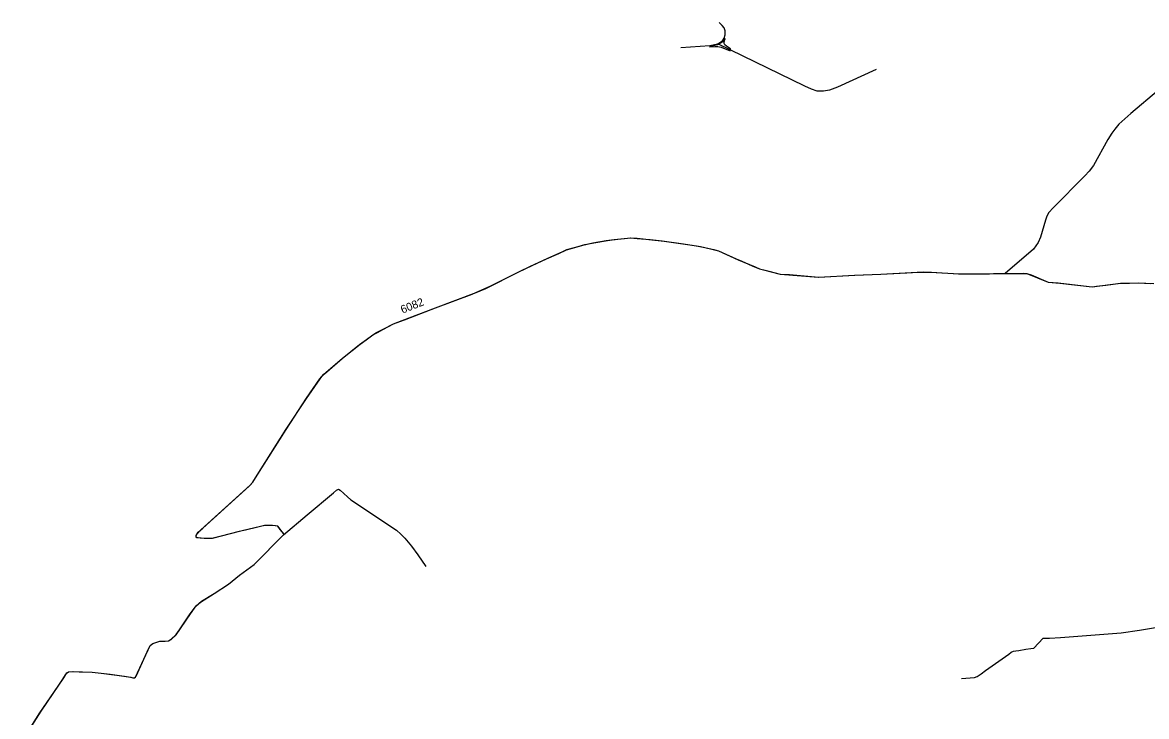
# Model space of a CAD drawing. Extents: x -444937 to -436355, y -1135022 to -1129798.
# Drawn here: x -444613 to -443209, y -1132915 to -1132048 of the extents above; entities that cross this region are included whole.
import ezdxf

# ---------------------------------------------------------------- set-up
doc = ezdxf.new("R2010")
doc.units = 0
doc.layers.add('Vrstva 12', color=7, linetype='Continuous')
doc.layers.add('Vrstva 75', color=7, linetype='Continuous')

msp = doc.modelspace()

# ---------------------------------------------------------------- linework, layer by layer
at = {"layer": 'Vrstva 12'}
for points in [[(-443790.5, -1132079.3), (-443754.5, -1132076.8), (-443744.6, -1132074.4), (-443738.7, -1132071), (-443736.3, -1132067.6), (-443735.4, -1132063.3), (-443735.4, -1132058.4), (-443736.6, -1132054.7), (-443739, -1132051.6), (-443742.8, -1132047.9)], [(-443546.4, -1132106.7), (-443594.8, -1132128.6), (-443605, -1132132.6), (-443612.4, -1132133.9), (-443620.1, -1132133.6), (-443627.5, -1132131.4), (-443635.5, -1132127.4), (-443744.6, -1132074.4)], [(-443193.7, -1132132.4), (-443228.1, -1132161.8), (-443243.2, -1132175.1), (-443248.2, -1132181.2), (-443252.1, -1132186.4), (-443257.1, -1132194.3), (-443275, -1132226.5), (-443280.2, -1132233.8), (-443285.8, -1132239.7), (-443325.5, -1132279.4), (-443330.7, -1132285.2), (-443333.2, -1132289.9), (-443335, -1132295.1), (-443341, -1132316.1), (-443344.2, -1132323), (-443350.1, -1132331.2), (-443385.1, -1132361.7)], [(-444286.4, -1132687.8), (-444291.4, -1132681.3), (-444294.5, -1132677.6), (-444297.8, -1132676.9), (-444301.8, -1132676.7), (-444311, -1132676.8), (-444317.7, -1132678.2), (-444337.3, -1132683), (-444376.8, -1132692.9), (-444381.9, -1132692.9), (-444386.3, -1132692.8), (-444390.1, -1132692.6), (-444391.2, -1132692.5), (-444394, -1132692.2), (-444394.6, -1132692.1), (-444395.8, -1132691.5), (-444396.3, -1132690.2), (-444396.3, -1132689.1), (-444395.6, -1132687.4), (-444390.6, -1132682), (-444328.9, -1132626.3), (-444325.6, -1132622.4), (-444322.2, -1132617.1), (-444284, -1132556.4), (-444258.4, -1132517.7), (-444241.6, -1132493.3), (-444239.4, -1132490.2), (-444236.1, -1132487), (-444213.9, -1132467.8), (-444192.2, -1132450.5), (-444183.6, -1132444.3), (-444175.6, -1132438.3), (-444169.9, -1132435.3), (-444163, -1132431.6), (-444149.6, -1132424.7), (-444139, -1132420.5), (-444097.1, -1132404.7), (-444046.4, -1132385.5), (-444034.5, -1132380.2), (-443993, -1132359.6), (-443976.4, -1132351.6), (-443958.6, -1132343.2), (-443943.2, -1132336.5), (-443933.5, -1132332.2), (-443923.2, -1132329), (-443913, -1132326.1), (-443900.5, -1132323.4), (-443884.1, -1132320.4), (-443873.9, -1132319.3)], [(-443873.9, -1132319.3), (-443860.9, -1132317.8), (-443853.7, -1132317.1), (-443845.1, -1132317.7), (-443829, -1132319.2), (-443813.9, -1132320.8), (-443787.5, -1132324.4), (-443774.1, -1132326.5), (-443765.9, -1132328.1), (-443753.7, -1132330.8), (-443743.6, -1132333.5), (-443718.8, -1132344.5), (-443697.9, -1132353.5), (-443692.3, -1132355.7), (-443687.3, -1132357), (-443666.5, -1132362.3), (-443654.9, -1132363.1), (-443618.1, -1132366.1), (-443573.6, -1132363.9), (-443540.7, -1132362.4), (-443508.2, -1132360.9), (-443493.5, -1132359.8), (-443478.8, -1132359.8), (-443442.9, -1132361.9), (-443404.8, -1132362.1), (-443385.1, -1132361.7), (-443362.3, -1132361.3), (-443358.1, -1132361.5), (-443353, -1132363.4), (-443331.5, -1132372.4), (-443319.2, -1132373.3), (-443276.5, -1132378.3), (-443271, -1132377.6), (-443259.7, -1132376.4), (-443241.2, -1132373.6), (-443230.1, -1132373.6), (-443218.9, -1132373.2), (-443203.8, -1132374.1)], [(-444613.4, -1132945.4), (-444590.2, -1132908.7), (-444567.2, -1132874.9), (-444563.8, -1132870), (-444559.6, -1132863.3), (-444557.8, -1132861), (-444556, -1132859.6), (-444550.6, -1132859.3), (-444542.8, -1132859.6), (-444526.3, -1132859.9), (-444515, -1132861.1), (-444486, -1132865.2), (-444478.6, -1132866.3), (-444475.4, -1132867), (-444473.5, -1132866.9), (-444472, -1132866.1), (-444454, -1132826.8), (-444450.4, -1132824.1), (-444445.7, -1132822.4), (-444441.8, -1132821.1), (-444435, -1132821.1), (-444430.8, -1132820.8), (-444427.7, -1132819.1), (-444421.2, -1132813.3), (-444403.6, -1132786.9), (-444396.3, -1132776.9), (-444390.9, -1132772.4), (-444374, -1132761.8), (-444355.9, -1132749.9), (-444342.4, -1132738.9), (-444323.9, -1132725.4), (-444287.2, -1132688.4), (-444257.5, -1132663.2), (-444224.7, -1132635.8), (-444220.9, -1132632.4), (-444218.5, -1132631.4), (-444216.2, -1132632.7), (-444211.7, -1132636.8), (-444207.2, -1132640.8), (-444202.9, -1132644.4), (-444146.1, -1132682.4), (-444140.4, -1132687.3), (-444135.5, -1132692.5), (-444127.1, -1132702.6), (-444119.5, -1132713.5), (-444109.5, -1132728.1)], [(-443439.9, -1132867.8), (-443423.7, -1132866.7), (-443420.1, -1132865.6), (-443415.5, -1132862.2), (-443409.8, -1132858), (-443380.8, -1132837.3), (-443377.7, -1132835.1), (-443374.7, -1132833.9), (-443371.9, -1132833.2), (-443368.2, -1132832.8), (-443359.4, -1132831.3), (-443353.1, -1132830.6), (-443349.3, -1132830.1), (-443338, -1132817.7), (-443334.6, -1132817.5), (-443330, -1132817.3), (-443316.2, -1132816.5), (-443240.3, -1132811), (-443217.5, -1132807.6), (-443192.3, -1132803.2)]]:
    msp.add_lwpolyline(points, dxfattribs=at)
msp.add_lwpolyline([(-443755, -1132078.3), (-443748.3, -1132077.9), (-443744.2, -1132078), (-443740.1, -1132078.9), (-443729, -1132083.2), (-443728.4, -1132080.7), (-443733.4, -1132077.4), (-443735.6, -1132075.6), (-443736.5, -1132074.1), (-443736.6, -1132072), (-443735.4, -1132068), (-443738.3, -1132072), (-443744.7, -1132075.7)], close=True, dxfattribs=at)
at = {"layer": 'Vrstva 75'}
for points in [[(-444286.2, -1132687.7), (-444291.4, -1132681.5), (-444294.5, -1132677.6), (-444297.1, -1132677), (-444301.1, -1132676.7), (-444310.3, -1132676.7), (-444314.3, -1132677.5), (-444319.4, -1132678.6), (-444334.8, -1132682.3), (-444342.5, -1132684.2), (-444376.4, -1132692.8), (-444385.1, -1132692.8), (-444390.9, -1132692.3), (-444394, -1132692.2), (-444395.5, -1132691.9), (-444396.4, -1132690.7), (-444396.3, -1132689.1), (-444393.8, -1132685.1), (-444388.2, -1132679.8), (-444330.1, -1132627.3), (-444325.6, -1132622.4), (-444322.2, -1132617.1), (-444284.1, -1132556.6), (-444258.5, -1132517.6), (-444241.9, -1132493.5), (-444239.4, -1132490.2), (-444237, -1132487.6), (-444213.5, -1132467.4), (-444191.4, -1132450), (-444183.9, -1132444.6), (-444175.6, -1132438.3), (-444170.8, -1132435.6), (-444162.5, -1132431.3), (-444149.6, -1132424.7), (-444136.2, -1132419.5), (-444097.1, -1132404.6), (-444051.4, -1132387.3), (-444028.3, -1132376.9), (-443993, -1132359.6), (-443978.7, -1132352.6), (-443957, -1132342.4), (-443938.2, -1132334.1), (-443933, -1132331.8), (-443921.8, -1132328.6), (-443910.6, -1132325.4), (-443897, -1132322.7), (-443882.1, -1132320.2), (-443876.5, -1132319.6)], [(-443876.5, -1132319.6), (-443865.6, -1132318.2), (-443853, -1132317.1), (-443845.1, -1132317.6), (-443826.9, -1132319.4), (-443811.3, -1132321.1), (-443785.2, -1132324.8), (-443771.1, -1132327), (-443762.6, -1132328.8), (-443749.6, -1132331.7), (-443743.6, -1132333.3), (-443721.3, -1132343.4), (-443714.3, -1132346.4), (-443701.3, -1132352.1), (-443692.3, -1132355.7), (-443680.6, -1132358.6), (-443666.5, -1132362.3), (-443618.4, -1132366.1), (-443573.2, -1132363.9), (-443540.7, -1132362.4), (-443495.2, -1132359.9), (-443487.2, -1132359.7), (-443477.2, -1132359.8), (-443443.5, -1132362.1), (-443427.3, -1132361.9), (-443399.8, -1132361.8), (-443358.1, -1132361.5), (-443331.5, -1132372.4), (-443317.1, -1132373.7), (-443276.5, -1132378.3), (-443241.2, -1132373.6), (-443218.9, -1132373.2), (-443199.5, -1132374.1)], [(-444613.4, -1132945.4), (-444592.4, -1132911.9), (-444569, -1132877.6), (-444561.9, -1132866.9), (-444557.9, -1132860.8), (-444555.7, -1132859.4), (-444550.1, -1132859.3), (-444526.3, -1132859.9), (-444503.9, -1132862.6), (-444477.9, -1132866.3), (-444475, -1132867), (-444473.5, -1132866.9), (-444472.8, -1132866.6), (-444471.5, -1132865.1), (-444459.6, -1132839), (-444457.5, -1132834.4), (-444456.7, -1132832.4), (-444455.7, -1132830.2), (-444454, -1132826.8), (-444450.4, -1132824.1), (-444441.8, -1132821.1), (-444430.8, -1132820.7), (-444427.6, -1132818.9), (-444421.2, -1132812.9), (-444417.3, -1132807.1), (-444404.6, -1132788.2), (-444396.3, -1132776.9), (-444389.5, -1132771.3), (-444374, -1132761.8), (-444355.9, -1132749.9), (-444342.4, -1132738.9), (-444323.9, -1132725.4), (-444286.2, -1132687.7)]]:
    msp.add_lwpolyline(points, dxfattribs=at)

# ---------------------------------------------------------------- texts
msp.add_text('6082', height=10, rotation=21.5484, dxfattribs=at).set_placement((-444138.5, -1132411.9))

doc.saveas('drawing.dxf')
